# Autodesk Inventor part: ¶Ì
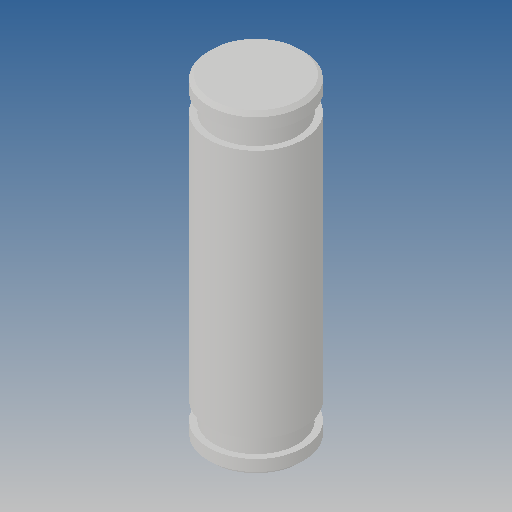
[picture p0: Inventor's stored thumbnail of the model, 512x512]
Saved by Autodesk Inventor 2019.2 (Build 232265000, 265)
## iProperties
Created: 2013-07
Part Number: ¶Ì
Material: Ogólny
Document SubType Name: Modeling
Designer: CADENGINEERING4
Density: 1 g/cm^3
Appearance: Domyślna
Author: CADENGINEERING4
Revision Number: ÈÎºÎ
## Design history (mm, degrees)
feature "CALC-63¶ÌÏú-1-solid1"
node "Bryła1"
